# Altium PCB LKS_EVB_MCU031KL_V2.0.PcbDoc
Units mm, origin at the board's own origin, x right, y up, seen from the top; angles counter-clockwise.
Board outline 66.67 x 39.62 mm, 2 copper layers (Top Layer, Bottom Layer); 57 components, 50 nets, 217 pads, 196 vias.
Unrouted connection lines stored in the file: 2.
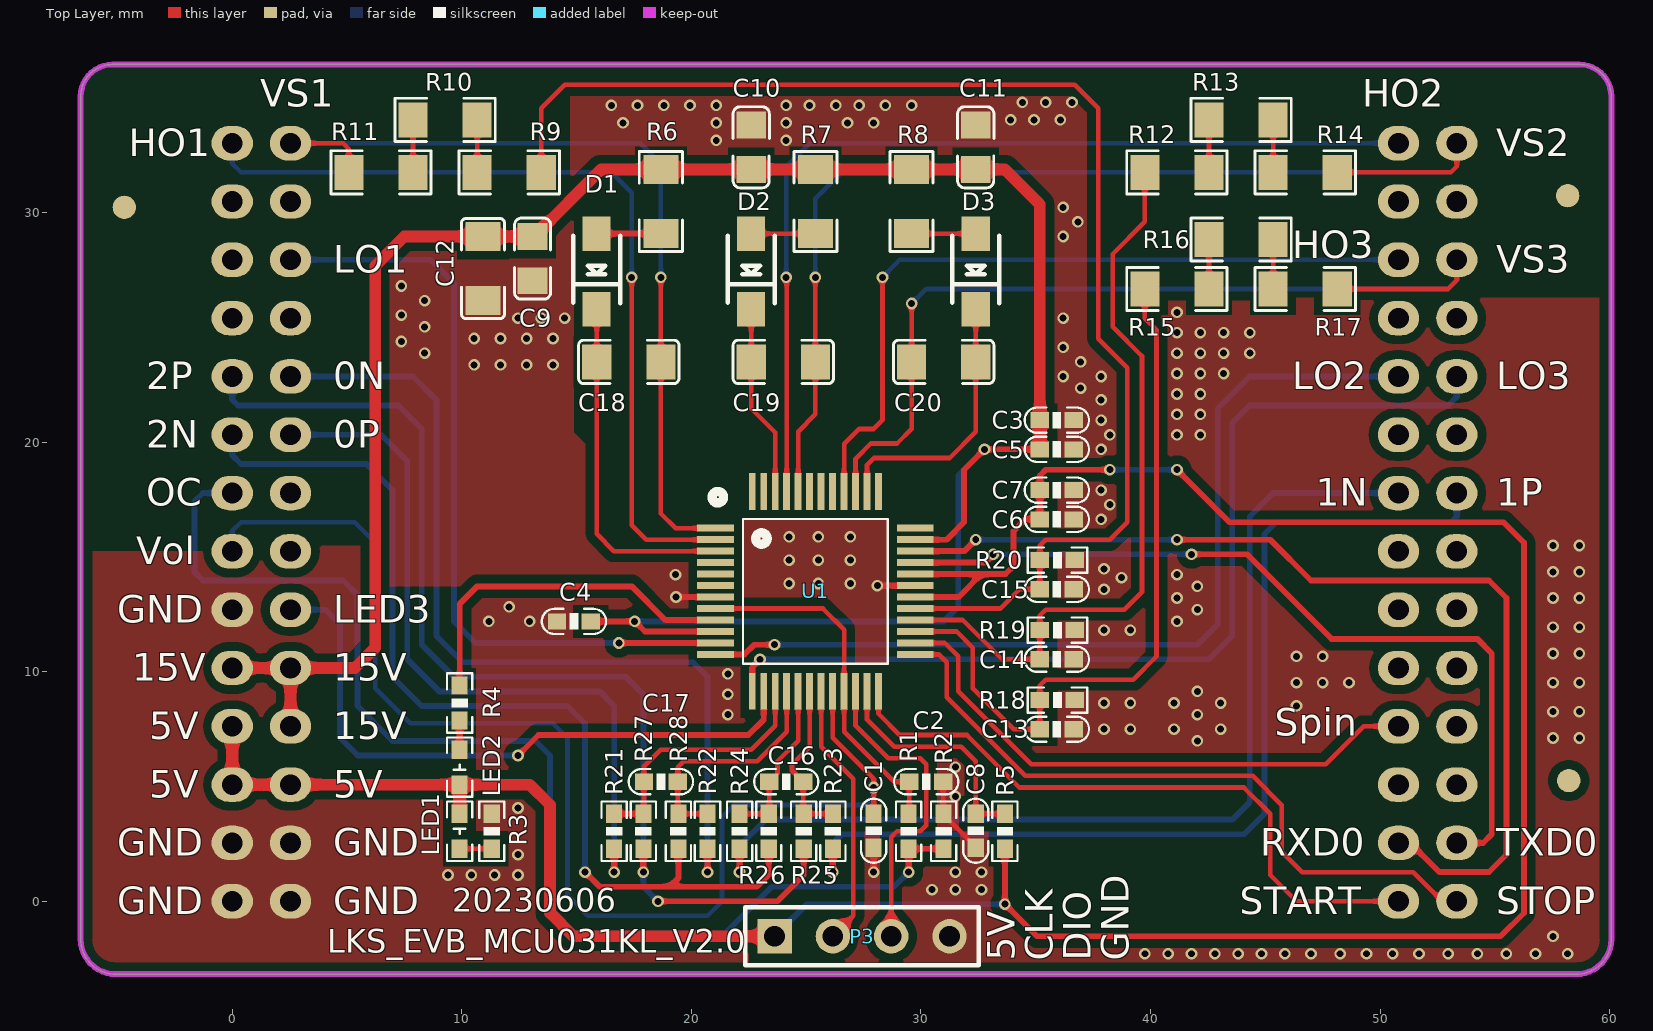
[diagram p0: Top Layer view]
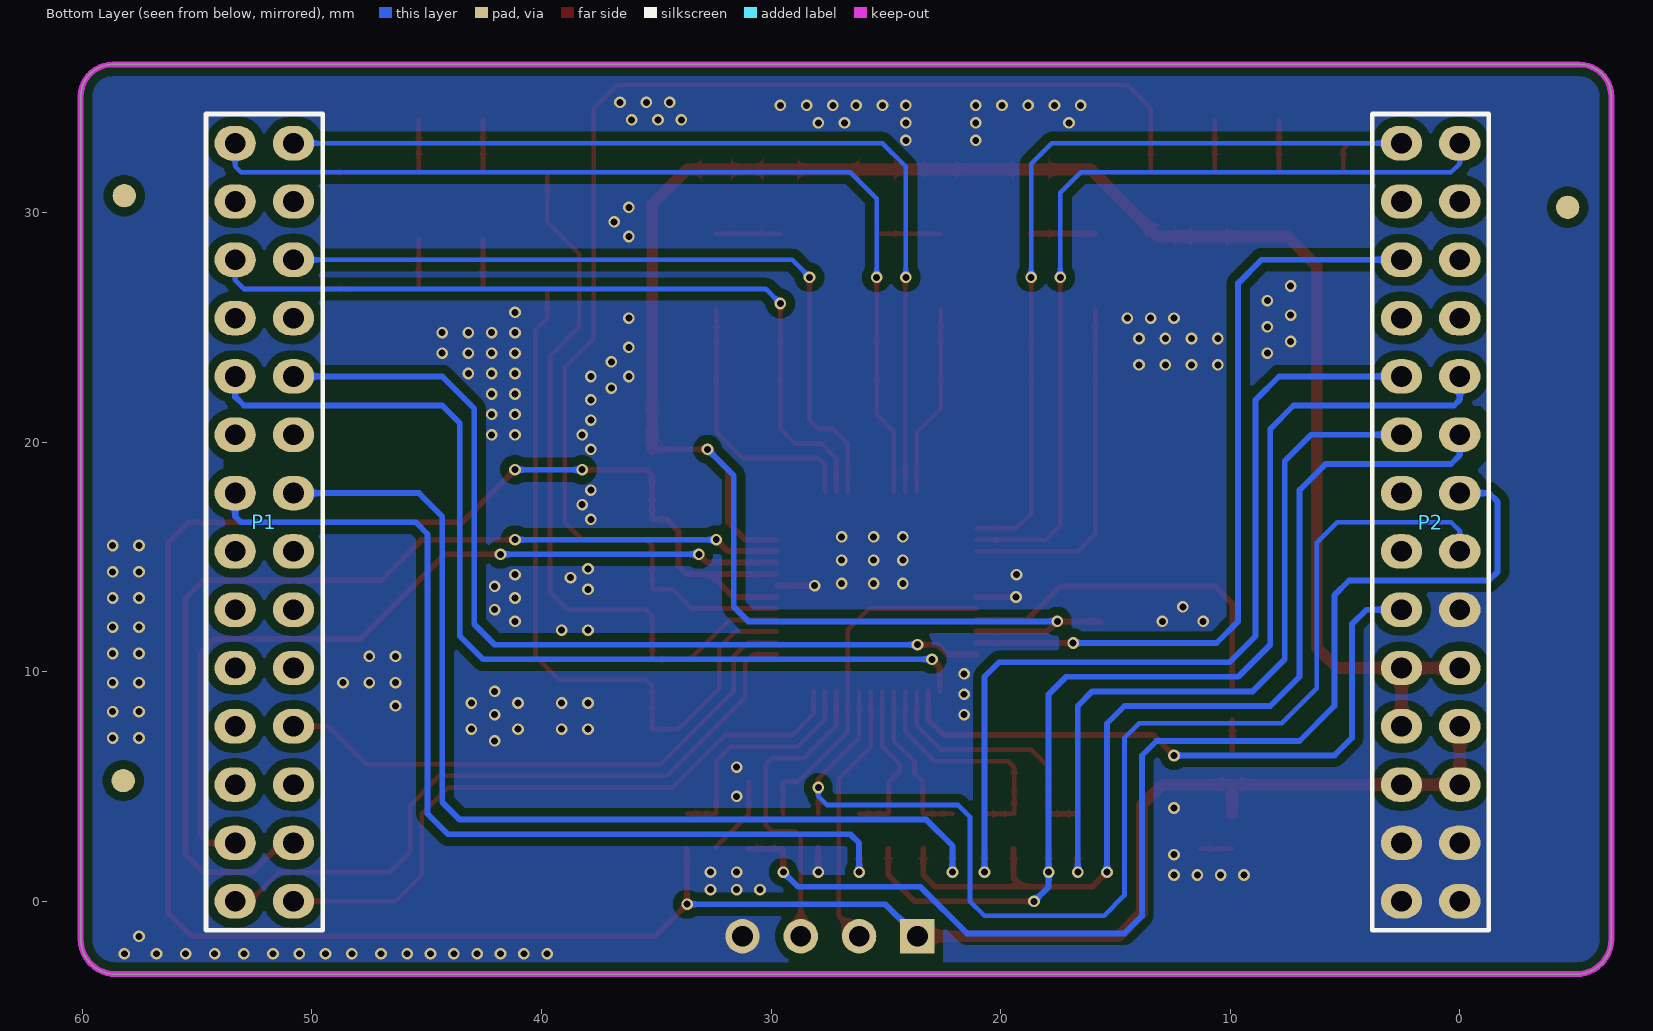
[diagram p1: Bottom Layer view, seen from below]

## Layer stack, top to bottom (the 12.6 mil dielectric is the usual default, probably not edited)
Top Solder: solder mask 0.0102, Solder Resist, Dk 3.5
Top Layer: signal copper 0.0356
Dielectric1: dielectric 0.32, FR-4, Dk 4.8
Bottom Layer: signal copper 0.0356
Bottom Solder: solder mask 0.0102, Solder Resist, Dk 3.5

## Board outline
-6.604,-1.651 -6.604,35.052 cw(c-5.207,35.052) -5.207,36.449 58.674,36.449 cw(c58.674,35.052) 60.071,35.052 60.071,-1.651 cw(c58.547,-1.651) 58.547,-3.175 -5.08,-3.175 cw(c-5.08,-1.651)

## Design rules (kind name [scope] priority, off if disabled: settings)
Clearance Polygon [InPolygon] p1: gap=0.381 ignorepadtopadclearanceinfootprint=FALSE
Clearance [All] p2: gap=0.127 ignorepadtopadclearanceinfootprint=FALSE
ComponentClearance [All] p1: gap=0 collisioncheckmode=3 verticalgap=0.254 showdistances=FALSE
DiffPairsRouting [All] p1: maxlimit=0.254 minlimit=0.254 mostfreqgap=0.254 substack1={F8E1A05F-7430-48D1-ADDB-6B3ABEC97D34} toplayer_{f8e1a05f-7430-48d1-addb-6b3abec97d34}_minwidth=0.381 toplayer_{f8e1a05f-7430-48d1-addb-6b3abec97d34}_maxwidth=0.381 toplayer_{f8e1a05f-7430-48d1-addb-6b3abec97d34}_prefwidth=0.381 bottomlayer_{f8e1a05f-7430-48d1-addb-6b3abec97d34}_minwidth=0.381 bottomlayer_{f8e1a05f-7430-48d1-addb-6b3abec97d34}_maxwidth=0.381 bottomlayer_{f8e1a05f-7430-48d1-addb-6b3abec97d34}_prefwidth=0.381 toplayer_minwidth=0.381 toplayer_maxwidth=0.381 toplayer_prefwidth=0.381 bottomlayer_minwidth=0.381 bottomlayer_maxwidth=0.381 bottomlayer_prefwidth=0.381 maxuncoupledlength=12.7
FabricationTestpoint [All] p1 off: side=3 testpointundercomponent=TRUE minsize=1.016 maxsize=2.54 preferedsize=1.524 minholesize=0 maxholesize=1.016 preferedholesize=0.813 testpointgrid=0.025 allowsidetop=TRUE allowsidebottom=TRUE usegrid=TRUE gridtolerance=0
FanoutControl Fanout_Small [All] p1 off: bgadir=Out bgaviamode=Centered fanoutstyle=Auto fanoutdirection=Alternating viagrid=0.025 // Protel DXP Scope 1 Expression Was: (CompPinCount < 5)   Fanout_Small (Default Rule)
FanoutControl Fanout_Default [All] p2: bgadir=Out bgaviamode=Centered fanoutstyle=Auto fanoutdirection=Alternating viagrid=0.025 // Fanout_Default (Default Rule)
FanoutControl Fanout_SOIC [All] p3 off: bgadir=Out bgaviamode=Centered fanoutstyle=Auto fanoutdirection=Alternating viagrid=0.025 // Protel DXP Scope 1 Expression Was: IsSOIC   Fanout_SOIC (Default Rule)
FanoutControl Fanout_BGA [All] p4 off: bgadir=Out bgaviamode=Centered fanoutstyle=Auto fanoutdirection=Alternating viagrid=0.025 // Protel DXP Scope 1 Expression Was: IsBGA   Fanout_BGA (Default Rule)
FanoutControl Fanout_LCC [All] p5 off: bgadir=Out bgaviamode=Centered fanoutstyle=Auto fanoutdirection=Alternating viagrid=0.025 // Protel DXP Scope 1 Expression Was: IsLCC   Fanout_LCC (Default Rule)
PolygonConnect [All] p1: connectstyle=Direct reliefconductorwidth=0.635 reliefentries=4 polygonreliefangle="90 Angle" airgapwidth=0.254
RoutingLayers [All] p1: top layer_v5=FALSE bottom layer_v5=FALSE
RoutingVias [All] p1: holewidth=0.508 width=1.27 viastyle="Through Hole" minholewidth=0 minwidth=0.457 maxholewidth=1.27 maxwidth=2.54
SilkToSolderMaskClearance [All] p1 off: minsilkscreentomaskgap=0.254 clearancetoexposedcopper=TRUE // Protel DXP Scope 1 Expression Was: IsPad
SolderMaskExpansion [All] p1: expansion=0.051 istentingtop=FALSE
Width [All] p1: maxlimit=2.54 minlimit=0.203 preferedwidth=0.249 substack1={F8E1A05F-7430-48D1-ADDB-6B3ABEC97D34} toplayer_{f8e1a05f-7430-48d1-addb-6b3abec97d34}_minwidth=0.229 bottomlayer_{f8e1a05f-7430-48d1-addb-6b3abec97d34}_minwidth=0.229 minimp=50.000000 maximp=50.000000 favimp=50.000000
20 further rules are at their usual default settings.

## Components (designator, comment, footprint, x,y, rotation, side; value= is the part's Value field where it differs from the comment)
C1 "100nF/50V" 0603C 27.94,3.072 r90 top
C2 "1nF/50V" 0603C 30.226,5.207 r180 top
C3 "4.7uF/25V" 0603C 35.917,20.955 r180 top
C4 "4.7uF/25V" 0603C 14.883,12.192 r0 top
C5 "4.7uF/25V" 0603C 35.917,19.685 r180 top
C6 "10uF/16V" 0603C 35.917,16.637 r180 top
C7 "100nF/50V" 0603C 35.917,17.907 r180 top
C8 "100nF/50V" 0603C 32.385,3.073 r270 top
C9 "100nF/50V" 0805C 13.081,27.991 r90 top
C10 "100nF/50V" 0805C 22.606,32.842 r270 top
C11 "100nF/50V" 0805C 32.385,32.842 r270 top
C12 "10uF/25V" 1206C 10.922,27.559 r270 top
C13 "1nF/16V" 0603C 35.917,7.493 r180 top
C14 "1nF/16V" 0603C 35.917,10.541 r180 top
C15 "1nF/16V" 0603C 35.917,13.589 r180 top
C16 "1uF/50V" 0603C 24.13,5.207 r180 top
C17 "100pF/50V" 0603C 18.669,5.207 r0 top
C18 "10uF/25V" 1206C 17.272,23.495 r0 top
C19 "10uF/25V" 1206C 24.003,23.495 r180 top
C20 "10uF/25V" 1206C 30.988,23.495 r180 top
D1 "US1J" SOD-123 15.875,27.431 r270 top
D2 "US1J" SOD-123 22.606,27.431 r270 top
D3 "US1J" SOD-123 32.385,27.431 r270 top
LED1 "LED" "LED 0603G" 9.906,3.048 r270 top
LED2 "LED" "LED 0603R" 9.906,5.842 r270 top
P1 "2X14" "HDR 2X14 底层" 50.8,33.02 r180 bottom
P2 "2X14" "HDR 2X14 底层" 0,33.02 r180 bottom
P3 "Header 4" "HDR 1X4" 23.622,-1.524 r0 top
R1 "1K1%" 0603R 29.464,3.048 r270 top value=K
R2 "10R" 0603R 30.988,3.048 r90 top value=10
R3 "2K" 0603R 11.303,3.048 r90 top value=330
R4 "2K" 0603R 9.906,8.636 r90 top value=330
R5 "20K" 0603R 33.655,3.048 r90 top value=K
R6 "4.7R" 1206R 18.669,30.48 r270 top
R7 "4.7R" 1206R 25.4,30.48 r270 top
R8 "4.7R" 1206R 29.591,30.48 r270 top
R9 "68K 1%" 1206R 12.065,31.75 r180 top
R10 "68K 1%" 1206R 9.271,34.036 r180 top
R11 "68K 1%" 1206R 6.477,31.75 r180 top
R12 "68K 1%" 1206R 41.148,31.75 r0 top
R13 "68K 1%" 1206R 43.942,34.036 r0 top
R14 "68K 1%" 1206R 46.736,31.75 r0 top
R15 "68K 1%" 1206R 41.148,26.67 r0 top
R16 "68K 1%" 1206R 43.942,28.829 r0 top
R17 "68K 1%" 1206R 46.736,26.67 r0 top
R18 "1K 1%" 0603R 35.941,8.763 r180 top value=K
R19 "1K 1%" 0603R 35.941,11.811 r180 top value=K
R20 "1K 1%" 0603R 35.941,14.859 r180 top value=K
R21 "1K 1%" 0603R 16.637,3.048 r90 top value=K
R22 "1K 1%" 0603R 20.701,3.048 r90 top value=K
R23 "1K 1%" 0603R 26.162,3.048 r90 top value=K
R24 "1K 1%" 0603R 22.098,3.048 r90 top value=K
R25 "1K 1%" 0603R 24.892,3.048 r90 top value=K
R26 "1K 1%" 0603R 23.368,3.048 r90 top value=K
R27 "1K 1%" 0603R 17.907,3.048 r90 top value=K
R28 "1K 1%" 0603R 19.431,3.048 r90 top value=K
U1 "LKS32MC031KLC6T8" TQFP48 25.4,13.5 r270 top locked

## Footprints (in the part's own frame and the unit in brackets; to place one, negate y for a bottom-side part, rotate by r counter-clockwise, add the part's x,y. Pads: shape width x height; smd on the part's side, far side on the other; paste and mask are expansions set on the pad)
0603C [mm] "电容"
  rect 0.8x0.7 smd: 1(-0.737,0) 2(0.738,0)
  silkscreen extent -1.4,-0.55 1.4,0.55, body extent -0.8,-0.41 0.8,0.41, height 0.81
0603R [mm] "电阻"
  rect 0.8x0.7 smd: 1(-0.762,0) 2(0.762,0)
  silkscreen extent -1.3,-0.55 1.3,0.55, body extent -0.8,-0.4 0.8,0.4, height 0.45
0805C [mil] "电容"
  rect 46x51.18 smd: 1(-38,0) 2(38,0)
  silkscreen extent -69,-31 70,31, body extent -39,-24 39,24, height 20
1206C [mil] "电容"
  rect 50x60 smd: 1(-55,0) 2(55,0)
  silkscreen extent -86,-37 86,37, body extent -63,-32 63,32, height 48
1206R [mil] "电阻"
  rect 50x60 smd: 1(-55,0) 2(55,0)
  silkscreen extent -86,-37 86,37, body extent -63,-31 63,32, height 24
"HDR 1X4" [mm] "单排针 2.54mm"
  rect 1.5x1.5 hole 0.9: 1(0,0)
  round 1.5 hole 0.9: 2(2.54,0) 3(5.08,0) 4(7.62,0)
  silkscreen extent -1.27,-1.27 8.89,1.27, body extent -1.27,-1.27 8.89,1.27, height 8.5
"HDR 2X14 底层" [mm] "双排针 2.54mm 底层"
  oval 1.8x1.5 hole 0.9: 1(0,0) 2(0,-2.54) 3(0,-5.08) 4(0,-7.62) 5(0,-10.16) 6(0,-12.7) 7(0,-15.24) 8(0,-17.78) 9(0,-20.32) 10(0,-22.86) 11(0,-25.4) 12(0,-27.94) 13(0,-30.48) 14(0,-33.02) 15(-2.54,0) 16(-2.54,-2.54) 17(-2.54,-5.08) 18(-2.54,-7.62) 19(-2.54,-10.16) 20(-2.54,-12.7) 21(-2.54,-15.24) 22(-2.54,-17.78) 23(-2.54,-20.32) 24(-2.54,-22.86) 25(-2.54,-25.4) 26(-2.54,-27.94) 27(-2.54,-30.48) 28(-2.54,-33.02)
  silkscreen extent -3.81,-34.29 1.27,1.27, body extent -3.81,-34.29 1.27,1.27, height 8.5
"LED 0603G" [mm] "LED"
  rect 0.8x0.7 smd: 1(-0.762,0) 2(0.762,0)
  silkscreen extent -1.3,-0.55 1.3,0.55, body extent -0.8,-0.4 0.8,0.4, height 0.47
"LED 0603R" [mm] "LED"
  rect 0.8x0.7 smd: 1(0.762,0) 2(-0.762,0)
  silkscreen extent -1.3,-0.55 1.3,0.55, body extent -0.8,-0.4 0.8,0.4, height 0.47
SOD-123 [mm] "二极管"
  rect 1.5x1.22 smd: 1(-1.65,0) 2(1.65,0)
  silkscreen extent -1.55,-1.03 1.38,1.02, body extent -1.85,-0.8 1.85,0.8, height 1.22
TQFP48 [mm] "LINKO-081/083/088/051"
  rect 0.3x1.6 smd: 1(-2.75,-4.35) 2(-2.25,-4.35) 3(-1.75,-4.35) 4(-1.25,-4.35) 5(-0.75,-4.35) 6(-0.25,-4.35) 7(0.25,-4.35) 8(0.75,-4.35) 9(1.25,-4.35) 10(1.75,-4.35) 11(2.25,-4.35) 12(2.75,-4.35) 25(2.75,4.35) 26(2.25,4.35) 27(1.75,4.35) 28(1.25,4.35) 29(0.75,4.35) 30(0.25,4.35) 31(-0.25,4.35) 32(-0.75,4.35) 33(-1.25,4.35) 34(-1.75,4.35) 35(-2.25,4.35) 36(-2.75,4.35)
  rect 1.6x0.3 smd: 13(4.35,-2.75) 14(4.35,-2.25) 15(4.35,-1.75) 16(4.35,-1.25) 17(4.35,-0.75) 18(4.35,-0.25) 19(4.35,0.25) 20(4.35,0.75) 21(4.35,1.25) 22(4.35,1.75) 23(4.35,2.25) 24(4.35,2.75) 37(-4.35,2.75) 38(-4.35,2.25) 39(-4.35,1.75) 40(-4.35,1.25) 41(-4.35,0.75) 42(-4.35,0.25) 43(-4.35,-0.25) 44(-4.35,-0.75) 45(-4.35,-1.25) 46(-4.35,-1.75) 47(-4.35,-2.25) 48(-4.35,-2.75)
  silkscreen extent -4.35,-4.5 3.15,3.15, body extent -4.5,-4.5 4.5,4.5, height 1.05

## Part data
C1 C2 C3 C4 C5 C6 C7 C8 C9 C10 C11 C16 C17: library part C, "Capacitor"
C12 C18 C19 C20: library part CAP
C13 C14 C15: library part CAP, "Capacitor"
D1 D2 D3: library part Diode, "Default Diode", PackageDocument=Sep-1996
LED1 LED2: "LED_Light"
P1 P2: "双排针"
P3: "Header, 4-Pin"
R1 R2 R3 R4 R5 R18 R19 R20 R21 R22 R23 R24 R25 R26 R27 R28: library part Res, "Resistor"
R6 R7 R8 R9 R10 R11 R12 R13 R14 R15 R16 R17: library part RES/1
U1: "芯片"

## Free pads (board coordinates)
  round 1.016 all layers, no hole: 3(-4.699,30.226) 3(58.166,30.734) 3(58.217,5.258)

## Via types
v1: diameter 0.508, hole 0.305, Top Layer to Bottom Layer, 196 vias

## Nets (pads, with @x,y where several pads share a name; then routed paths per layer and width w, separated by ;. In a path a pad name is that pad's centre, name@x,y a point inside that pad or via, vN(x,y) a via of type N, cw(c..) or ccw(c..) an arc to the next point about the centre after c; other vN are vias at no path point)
+5V: C6.2 C7.2 LED1.1 LED2.1 P2.11 P2.12 P2.26 P3.1 R5.1 U1.30 U1.32 | length 120.7
  Top Layer w0.254: U1.30 31.639,13.25 32.639,14.25 ; U1.32 32.639,14.25 ; R5.1 v1(33.655,-0.127) 35.052,-1.524 55.245,-1.524 56.261,-0.508 56.261,15.621 55.372,16.51 43.434,16.51 v1(41.148,18.796) ; v1(38.227,18.796) 35.433,18.796 35.179,18.542 C7.2 C6.2 34.544,16.637 34.036,16.129 34.036,14.605 33.681,14.25 32.639,14.25
  Top Layer w0.508: P2.11 P2.12 P2.26 LED2.1 ; LED1.1 LED2.1 ; P3.1 14.859,-1.524 13.843,-0.508 13.843,4.191 12.954,5.08 LED2.1
  Bottom Layer w0.254: P3.1 25.019,-0.127 v1(33.655,-0.127) ; v1(38.227,18.796) v1(41.148,18.796)
+15V: C3.2 C4.2 C5.2 C9.2 C10.2 C11.2 C12.1 P2.10 P2.24 P2.25 R6.1 R7.1 R8.1 U1.10 U1.35 | length 103.5
  Top Layer w0.254: C4.2 v1(17.526,12.192) 17.54,12.192 17.982,11.75 U1.10 ; U1.35 31.117,15.75 31.877,16.51 31.877,18.796 v1(32.766,19.685) C5.2
  Top Layer w0.508: P2.10 P2.24 ; P2.25 P2.24 ; C5.2 C3.2 35.179,30.353 33.655,31.877 C11.2 R8.1 R7.1 C10.2 R6.1 16.068,31.877 13.147,28.956 C9.2 C12.1 7.493,28.956 6.223,27.686 6.223,11.049 5.334,10.16 P2.24
  Bottom Layer w0.254: v1(17.526,12.192) 30.988,12.192 31.623,12.827 31.623,18.542 v1(32.766,19.685)
BEMF_U: C15.2 R9.1 R20.2 U1.29 | length 58.4
  Top Layer w0.203: R9.1 13.462,34.544 14.478,35.56 36.703,35.56 37.719,34.544 37.719,24.511 38.989,23.241 38.989,16.51 38.227,15.748 35.433,15.748 35.179,15.494 R20.2 C15.2 34.29,13.589 33.451,12.75 U1.29
BEMF_V: C14.2 R12.1 R19.2 U1.28 | length 32.3
  Top Layer w0.203: U1.28 31.819,12.25 33.528,10.541 C14.2 R19.2 35.179,12.446 35.433,12.7 38.862,12.7 39.624,13.462 39.624,23.749 38.354,25.019 38.354,28.194 39.751,29.591 R12.1
BEMF_W: C13.2 R15.1 R18.2 U1.27 | length 32
  Top Layer w0.203: U1.27 31.557,11.75 32.258,11.049 32.258,9.271 34.036,7.493 C13.2 R18.2 35.179,9.398 35.433,9.652 39.243,9.652 40.259,10.668 40.259,24.892 39.751,25.4 R15.1
FO: R4.2 U1.9 | length 15.6
  Top Layer w0.254: R4.2 9.906,12.954 10.668,13.716 17.399,13.716 18.865,12.25 U1.9
GND: C1.1 C2.1 C3.1 C4.1 C5.1 C6.1 C7.1 C8.2 C9.1 C10.1 C11.1 C12.2 C13.1 C14.1 C15.1 P2.6 P2.9 P2.13 P2.14 P2.27 P2.28 P3.4 R2.2 R3.2 R18.1 R19.1 R20.1 R26.1 R28.1 U1.7 U1.31 | length 51.7
  Top Layer w0.203: C2.1 30.963,3.835 R2.2 30.988,3.76 32.114,2.634 32.137,2.634 32.385,2.385 C8.2
  Top Layer w0.254: v1(15.367,1.27) 16.002,0.635 19.05,0.635 ; v1(19.33,13.251) U1.7 ; R28.1 19.431,1.016 19.05,0.635 ; R26.1 23.368,1.143 22.86,0.635 19.05,0.635 ; v1(27.94,1.27) C1.1 ; v1(28.101,13.75) U1.31
  Bottom Layer w0.254: P2.6 0,19.431 0.381,19.05 5.842,19.05 6.985,17.907 6.985,9.779 8.255,8.509 14.605,8.509 15.367,7.747 v1(15.367,1.27)
  other v1: 39.751,-2.286 40.767,-2.286 41.783,-2.286 42.799,-2.286 43.815,-2.286 44.831,-2.286 45.847,-2.286 46.99,-2.286 48.26,-2.286 49.403,-2.286 50.546,-2.286 51.689,-2.286 52.959,-2.286 54.229,-2.286 55.499,-2.286 56.769,-2.286 58.166,-2.286 57.531,-1.524 30.48,0.508 31.496,0.508 32.639,0.508 9.398,1.143 10.414,1.143 11.43,1.143 12.446,1.143 31.496,1.27 32.639,1.27 12.446,2.032 12.446,4.064 31.496,4.572 31.496,5.842 42.037,6.985 57.531,7.112 58.674,7.112 37.973,7.493 39.116,7.493 41.021,7.493 43.053,7.493 21.59,8.128 42.037,8.128 57.531,8.255 58.674,8.255 46.355,8.509 37.973,8.636 39.116,8.636 41.021,8.636 43.053,8.636 21.59,9.017 42.037,9.144 46.355,9.525 47.498,9.525 48.641,9.525 57.531,9.525 58.674,9.525 21.59,9.906 46.355,10.668 47.498,10.668 57.531,10.795 58.674,10.795 37.973,11.811 39.116,11.811 57.531,11.938 58.674,11.938 11.176,12.192 12.954,12.192 41.148,12.192 42.037,12.7 12.065,12.827 41.148,13.208 57.531,13.208 58.674,13.208 37.973,13.589 42.037,13.716 24.257,13.843 25.527,13.843 26.924,13.843 38.735,14.097 19.304,14.224 41.148,14.224 57.531,14.351 58.674,14.351 37.973,14.478 24.257,14.859 25.527,14.859 26.924,14.859 57.531,15.494 58.674,15.494 24.257,15.875 25.527,15.875 26.924,15.875 37.846,16.637 38.227,17.272 37.846,17.907 37.846,19.685 38.227,20.32 41.148,20.32 42.164,20.32 37.846,20.955 41.148,21.209 42.164,21.209 37.846,21.844 41.148,22.098 42.164,22.098 36.957,22.352 36.195,22.86 37.846,22.86 41.148,22.987 42.164,22.987 43.18,22.987 10.541,23.368 11.684,23.368 12.827,23.368 13.97,23.368 36.957,23.495 8.382,23.876 41.148,23.876 42.164,23.876 43.18,23.876 44.323,23.876 36.195,24.13 7.366,24.384 10.541,24.511 11.684,24.511 12.827,24.511 13.97,24.511 41.148,24.765 42.164,24.765 43.18,24.765 44.323,24.765 8.382,25.019 12.446,25.4 13.462,25.4 14.478,25.4 36.195,25.4 7.366,25.527 41.148,25.654 8.382,26.162 7.366,26.797 36.195,28.956 36.83,29.591 36.195,30.226 21.082,33.147 24.13,33.147 17.018,33.909 21.082,33.909 24.13,33.909 26.797,33.909 27.94,33.909 33.909,34.036 34.925,34.036 36.068,34.036 16.51,34.671 17.653,34.671 18.796,34.671 19.939,34.671 21.082,34.671 24.13,34.671 25.146,34.671 26.289,34.671 27.305,34.671 28.448,34.671 29.591,34.671 34.417,34.798 35.433,34.798 36.576,34.798
HO1: P2.1 U1.2 | length 37.2
  Top Layer w0.203: v1(17.399,27.178) 17.399,16.383 18.032,15.75 U1.2
  Bottom Layer w0.203: P2.1 0,32.131 0.381,31.75 16.51,31.75 17.399,30.861 v1(17.399,27.178)
HO2: P1.1 U1.45 | length 41.3
  Top Layer w0.203: v1(24.13,27.178) 24.15,27.158 U1.45
  Bottom Layer w0.203: v1(24.13,27.178) 24.13,32.004 25.146,33.02 P1.1
HO3: P1.3 U1.40 | length 33.2
  Top Layer w0.203: U1.40 26.65,19.919 27.305,20.574 27.94,20.574 28.321,20.955 v1(28.321,27.178)
  Bottom Layer w0.203: v1(28.321,27.178) 29.083,27.94 P1.3
LED3: P2.23 U1.14 | length 28
  Top Layer w0.254: v1(12.446,6.35) 13.335,7.239 22.479,7.239 23.15,7.91 U1.14
  Bottom Layer w0.254: P2.23 4.064,12.7 4.699,12.065 4.699,7.112 5.461,6.35 v1(12.446,6.35)
LO1: P2.17 U1.11 | length 34.1
  Top Layer w0.254: v1(16.838,11.25) U1.11
  Bottom Layer w0.254: P2.17 8.636,27.94 9.652,26.924 9.652,12.192 10.594,11.25 v1(16.838,11.25)
LO2: P1.5 U1.12 | length 40.3
  Top Layer w0.254: U1.12 22.307,10.75 22.733,11.176 v1(23.622,11.176)
  Bottom Layer w0.254: v1(23.622,11.176) 42.037,11.176 42.926,12.065 42.926,21.463 44.323,22.86 P1.5
LO3: P1.19 U1.13 | length 42.9
  Top Layer w0.254: U1.13 22.65,10.204 v1(22.987,10.541)
  Bottom Layer w0.254: v1(22.987,10.541) 42.545,10.541 43.561,11.557 43.561,20.828 44.323,21.59 52.959,21.59 53.34,21.971 P1.19
NetD1_1: D1.1 R6.2 | length 2.8
  Top Layer w0.254: D1.1 15.877,29.083 R6.2
NetD2_1: D2.1 R7.2 | length 2.8
  Top Layer w0.203: D2.1 25.398,29.081 R7.2
NetD3_1: D3.1 R8.2 | length 2.8
  Top Layer w0.203: R8.2 29.593,29.081 D3.1
NetLED1_2: LED1.2 R3.1 | length 1.4
  Top Layer w0.203: LED1.2 R3.1
NetLED2_2: LED2.2 R4.1 | length 1.3
  Top Layer w0.254: LED2.2 R4.1
NetR9_2: R9.2 R10.1 | length 2.3
  Top Layer w0.203: R9.2 R10.1
NetR10_2: R10.2 R11.1 | length 2.3
  Top Layer w0.203: R11.1 R10.2
NetR12_2: R12.2 R13.1 | length 2.3
  Top Layer w0.203: R12.2 R13.1
NetR13_2: R13.2 R14.1 | length 2.3
  Top Layer w0.203: R14.1 R13.2
NetR15_2: R15.2 R16.1 | length 2.2
  Top Layer w0.203: R15.2 R16.1
NetR16_2: R16.2 R17.1 | length 2.2
  Top Layer w0.203: R17.1 R16.2
NRST: C8.1 R5.2 U1.23 | length 10.3
  Top Layer w0.203: U1.23 27.65,7.91 28.829,6.731 31.75,6.731 32.385,6.096 C8.1 R5.2
OC: C2.2 R1.1 U1.8 U1.21 | length 15.6
  Top Layer w0.203: U1.8 25.731,12.75 26.65,11.831 U1.21 26.65,7.386 28.829,5.207 C2.2 29.488,3.834 R1.1
OPA0_IN: C16.2 R24.2 R26.2 U1.17 | length 7.1
  Top Layer w0.203: R24.2 R26.2 23.392,3.834 C16.2 23.749,5.564 23.749,6.096 24.65,6.997 U1.17
OPA0_IP: C16.1 R23.2 R25.2 U1.18 | length 7.1
  Top Layer w0.203: U1.18 25.15,6.735 24.384,5.969 24.384,5.69 C16.1 24.867,3.835 R25.2 R23.2
OPA1_IN: C17.2 R22.2 R28.2 U1.16 | length 10.5
  Top Layer w0.203: R22.2 R28.2 19.407,3.834 C17.2 19.407,5.842 19.661,6.096 22.86,6.096 24.15,7.386 U1.16
OPA1_IP: C17.1 R21.2 R27.2 U1.15 | length 11.3
  Top Layer w0.203: R27.2@17.932,3.835 C17.1 17.932,5.867 18.669,6.604 22.606,6.604 23.65,7.648 U1.15
  Top Layer w0.229: R21.2 R27.2 R27.2@17.932,3.835
RXD0: P1.13 U1.34 | length 43.7
  Top Layer w0.254: U1.34 31.887,15.25 v1(32.385,15.748) ; v1(41.148,15.748) 45.212,15.748 46.99,13.97 54.737,13.97 55.499,13.208 55.499,2.032 54.737,1.27 52.578,1.27 51.308,2.54 P1.13
  Bottom Layer w0.254: v1(32.385,15.748) v1(41.148,15.748)
SHUNT: P2.5 P2.7 R1.2 R2.1 R25.1 R27.1 | length 101.1
  Top Layer w0.254: v1(17.907,1.27) R27.1 ; v1(18.542,0) 23.749,0 24.892,1.143 R25.1 ; v1(29.464,1.27) R1.2 R2.1
  Bottom Layer w0.254: P2.7 -1.27,17.78 -1.651,17.399 -1.651,14.351 -1.27,13.97 4.826,13.97 5.461,13.335 5.461,8.509 6.985,6.985 13.208,6.985 13.843,6.35 13.843,-0.635 14.605,-1.397 21.463,-1.397 23.495,0.635 28.829,0.635 v1(29.464,1.27) ; P2.5 0,21.844 0.254,21.59 7.239,21.59 8.255,20.574 8.255,11.176 9.652,9.779 17.145,9.779 17.907,9.017 v1(17.907,1.27) 17.907,0.635 v1(18.542,0)
SHUNT0: P2.19 R22.1 | length 39.1
  Top Layer w0.254: v1(20.701,1.27) R22.1
  Bottom Layer w0.254: P2.19 7.874,22.86 8.89,21.844 8.89,11.557 10.033,10.414 20.066,10.414 20.701,9.779 v1(20.701,1.27)
SHUNT1: P1.7 R24.1 | length 44.5
  Top Layer w0.254: v1(22.098,1.27) R24.1
  Bottom Layer w0.254: v1(22.098,1.27) 22.098,2.413 23.241,3.556 43.561,3.556 44.323,4.318 44.323,16.764 45.339,17.78 P1.7
SHUNT_U: P2.20 R21.1 | length 32.3
  Top Layer w0.254: v1(16.637,1.27) R21.1
  Bottom Layer w0.254: P2.20 6.477,20.32 7.62,19.177 7.62,10.541 9.017,9.144 16.002,9.144 16.637,8.509 v1(16.637,1.27)
SHUNT_V: P1.21 R23.1 | length 43.5
  Top Layer w0.254: v1(26.162,1.27) R23.1
  Bottom Layer w0.254: v1(26.162,1.27) 26.162,2.54 26.543,2.921 44.069,2.921 44.958,3.81 44.958,16.002 45.466,16.51 53.086,16.51 53.34,16.764 P1.21
SPIN: P1.11 U1.26 | length 24.8
  Top Layer w0.203: U1.26 31.041,11.25 31.623,10.668 31.623,9.144 34.798,5.969 47.625,5.969 49.276,7.62 P1.11
START1: P1.14 U1.24 | length 28.6
  Top Layer w0.203: U1.24 28.15,8.172 29.083,7.239 32.004,7.239 34.29,4.953 44.069,4.953 45.212,3.81 45.212,1.143 46.355,0 P1.14
STOP1: P1.28 U1.25 | length 30.1
  Top Layer w0.203: U1.25 30.779,10.75 31.115,10.414 31.115,8.89 34.544,5.461 44.45,5.461 45.72,4.191 45.72,2.159 46.609,1.27 51.435,1.27 52.705,0 53.19,0 P1.28
SWCLK: P3.2 U1.19 | length 11.6
  Top Layer w0.203: U1.19 25.65,6.735 27.051,5.334 27.051,-0.635 P3.2
SWDIO: P3.3 U1.22 | length 14
  Top Layer w0.203: U1.22 27.15,7.648 28.575,6.223 29.972,6.223 30.226,5.969 30.226,3.302 29.972,3.048 28.956,3.048 28.702,2.794 P3.3
TXD0: P1.27 U1.33 | length 36.6
  Top Layer w0.254: U1.33 32.784,14.75 v1(33.147,15.113) ; v1(41.783,15.113) 44.196,15.113 47.879,11.43 54.229,11.43 54.864,10.795 54.864,2.921 54.483,2.54 P1.27
  Bottom Layer w0.254: v1(33.147,15.113) v1(41.783,15.113)
VB1: C18.1 D1.2 U1.3 | length 15.3
  Top Layer w0.203: D1.2 C18.1 15.875,16.002 16.627,15.25 U1.3
VB2: C19.2 D2.2 U1.46 | length 8.4
  Top Layer w0.203: D2.2 C19.2 22.606,21.463 23.65,20.419 U1.46
VB3: C20.1 D3.2 U1.38 | length 11.8
  Top Layer w0.203: U1.38 27.65,19.014 27.94,19.304 31.242,19.304 32.385,20.447 C20.1 D3.2
VOL_ADC: C1.2 P2.8 U1.20 | length 54.6
  Top Layer w0.203: U1.20 26.15,7.124 27.94,5.334 v1(27.94,4.953) C1.2
  Bottom Layer w0.203: P2.8 0,16.129 0.381,16.51 5.334,16.51 6.223,15.621 6.223,9.271 7.747,7.747 13.97,7.747 14.605,7.112 14.605,0.254 15.494,-0.635 20.701,-0.635 21.336,0 21.336,3.683 21.844,4.191 27.559,4.191 27.939,4.571 27.939,4.952 v1(27.94,4.953)
VS1: C18.2 P2.15 R11.2 U1.1 | length 38
  Top Layer w0.203: P2.15 4.826,33.02 5.08,32.766 R11.2 ; v1(18.669,27.178) C18.2 18.669,16.891 19.31,16.25 U1.1
  Bottom Layer w0.203: P2.15 17.78,33.02 18.669,32.131 v1(18.669,27.178)
VS2: C19.1 P1.15 R14.2 U1.44 | length 48.9
  Top Layer w0.203: U1.44 24.65,20.459 25.4,21.209 C19.1 v1(25.4,27.178) ; R14.2 53.086,31.75 53.34,32.004 P1.15
  Bottom Layer w0.203: v1(25.4,27.178) 25.4,30.607 26.543,31.75 53.086,31.75 53.34,32.004 P1.15
VS3: C20.2 P1.17 R17.2 U1.39 | length 41.2
  Top Layer w0.203: U1.39 27.15,19.276 27.813,19.939 28.956,19.939 29.591,20.574 C20.2 v1(29.591,26.035) ; R17.2 52.959,26.67 53.34,27.051 P1.17
  Bottom Layer w0.203: v1(29.591,26.035) 30.226,26.67 52.959,26.67 53.34,27.051 P1.17
pads on no net: P1.2 P1.4 P1.6 P1.8 P1.9 P1.10 P1.12 P1.16 P1.18 P1.20 P1.22 P1.23 P1.24 P1.25 P1.26 P2.2 P2.3 P2.4 P2.16 P2.18 P2.21 P2.22 U1.4 U1.5 U1.6 U1.36 U1.37 U1.41 U1.42 U1.43 U1.47 U1.48

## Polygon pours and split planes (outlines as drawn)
GND on Top Layer "10" (solid, remove dead copper, pour order 1): -6.604,36.449 -6.604,-3.175 60.071,-3.175 60.071,36.449
GND on Bottom Layer "10" (solid, remove dead copper, pour order 0): -6.604,36.449 -6.604,-3.175 60.071,-3.175 60.071,36.449

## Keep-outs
Keep-Out Layer:
  the board outline again, w0.254

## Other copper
Top Layer:
  pour cut-out: 36.576,26.416 43.307,26.416 43.434,26.543 58.928,26.543 58.928,36.703 36.576,36.703
  pour cut-out: 10.668,13.716 6.096,13.716 6.096,12.7 9.652,12.7
  pour cut-out: 13.081,28.956 14.732,30.607 14.732,35.814 14.097,36.449 -6.604,36.449 -6.604,15.24 2.54,15.24 2.794,15.494 6.223,15.494 6.223,27.686 7.493,28.956
  pour cut-out: 14.859,30.734 14.884,30.709 14.884,20.422 16.637,18.669 33.655,18.669 35.179,20.193 35.179,30.353 33.528,32.004 16.195,32.004 16.068,31.877
  pour cut-out: 22.86,3.048 22.86,1.143 22.606,0.889 20.32,0.889 20.066,1.143 20.066,2.794 19.939,2.921 18.923,2.921 18.796,2.794 18.796,1.143 18.542,0.889 16.256,0.889 15.748,1.397 15.748,2.413 14.986,2.413 14.986,0.762 15.367,0.381 23.114,0.381 23.876,1.143 23.876,3.048
Bottom Layer:
  pour cut-out: 53.34,20.32 53.34,17.78 53.467,17.653 53.848,17.653 53.848,20.193 53.975,20.32
  pour cut-out: -0.889,21.59 -1.27,21.209 -1.27,19.304 -0.635,18.669 5.334,18.669 6.477,17.526 6.477,9.525 7.874,8.128 14.351,8.128 14.986,7.493 14.986,0.572 15.748,0.572 15.748,8.128 14.986,8.89 8.636,8.89 7.366,10.16 7.366,18.415 6.223,19.558 1.651,19.558 1.27,19.939 1.27,21.209 0.889,21.59

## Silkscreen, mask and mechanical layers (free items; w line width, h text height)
Top Overlay:
  text "VS1" at 1.216,34.617 h1.2
  text "HO2" at 49.222,34.617 h1.2
  text "HO1" at -4.499,32.458 h1.2
  text "VS2" at 55.064,32.458 h1.2
  text "HO3" at 46.174,28.013 h1.2
  text "LO1" at 4.391,27.378 h1.2
  text "VS3" at 55.064,27.378 h1.2
  text "2P" at -3.737,22.298 h1.2
  text "0N" at 4.391,22.298 h1.2
  text "LO2" at 46.174,22.298 h1.2
  text "LO3" at 55.064,22.298 h1.2
  text "2N" at -3.737,19.758 h1.2
  text "0P" at 4.391,19.758 h1.2
  text "OC" at -3.737,17.218 h1.2
  text "1N" at 47.19,17.218 h1.2
  text "1P" at 55.064,17.218 h1.2
  text "Vol" at -4.179,14.678 h1.2
  text "GND" at -5.007,12.138 h1.2
  text "LED3" at 4.391,12.138 h1.2
  text "15V" at -4.345,9.598 h1.2
  text "15V" at 4.391,9.598 h1.2
  text "Spin" at 45.412,7.204 h1.2
  text "5V" at -3.625,7.058 h1.2
  text "15V" at 4.391,7.058 h1.2
  text "5V" at -3.625,4.518 h1.2
  text "5V" at 4.391,4.518 h1.2
  text "GND" at -5.007,1.978 h1.2
  text "GND" at 4.391,1.978 h1.2
  text "RXD0" at 44.777,1.978 h1.2
  text "TXD0" at 55.064,1.978 h1.2
  text "20230606" at 9.576,-0.457 h1.02
  text "GND" at -5.007,-0.562 h1.2
  text "GND" at 4.391,-0.562 h1.2
  text "START" at 43.888,-0.562 h1.2
  text "STOP" at 55.064,-0.562 h1.2
  text "LKS_EVB_MCU031KL_V2.0" at 4.14,-2.252 h1.02
  text "5V" at 34.09,-2.594 h1.2 r90
  text "CLK" at 35.741,-2.594 h1.2 r90
  text "DIO" at 37.392,-2.594 h1.2 r90
  text "GND" at 39.043,-2.594 h1.2 r90
Top Solder:
  circle w1.981: c58.217,5.258 r0.432
  circle w1.981: c-4.699,30.226 r0.432
  circle w1.981: c58.166,30.734 r0.432
Mechanical 1:
  the board outline again, w0.254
